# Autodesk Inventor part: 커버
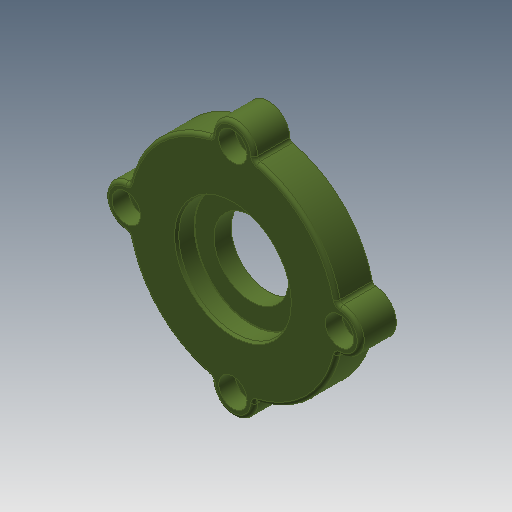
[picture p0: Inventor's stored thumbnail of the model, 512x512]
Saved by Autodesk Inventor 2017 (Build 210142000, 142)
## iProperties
Created: 2016-06
Part Number: 커버
Material: 알루미늄 6061
Document SubType Name: Modeling
Designer: mduedu
Density: 2.71 g/cm^3
Appearance: 올리브 녹색
Author: mduedu
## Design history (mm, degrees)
sketch "스케치1"
  geometry: C1 r 30 at (0, 0); 1 further point
  constraints: 1 centre point, 1 coincident
  dimensions: "d0" = 60 diameter of C1
extrude "돌출1" new body sketch "스케치1" distance "d2" = 10; taper "d3" = 0 deg
sketch "스케치5"
  geometry: C1 r 6 at (0, 30); 2 further points
  constraints: 2 vertical alignment, 1 centre point, 1 other
  dimensions: "d61" = 12 diameter of C1
extrude "돌출3" join sketch "스케치5" stored distance "d62" = 10; taper "d63" = 0 deg
sketch "스케치2"
  geometry: C1 r 21 at (0, 0); 1 further point
  constraints: 1 centre point, 1 coincident
  dimensions: "d4" = 42 diameter of C1
extrude "돌출2" join sketch "스케치2" distance "d6" = 3; taper "d7" = 0 deg
hole "구멍1" diameter "d11" = 35; stored, may be unused: countersink angle "d15" = 90 deg, drill point angle "d17" = 0 deg; dims "d9" = 10, "d10" = 10, "d12" = 6, "d13" = 4, "d14" = 2, "d16" = 3
hole "구멍2" diameter "d20" = 32; stored, may be unused: countersink angle "d24" = 90 deg, drill point angle "d26" = 0 deg; dims "d21" = 6, "d22" = 4, "d23" = 2, "d25" = 5.2, "d67" = 10, "d68" = 10
hole "구멍3" diameter "d29" = 21; stored, may be unused: countersink angle "d33" = 90 deg, drill point angle "d35" = 0 deg; dims "d27" = 10, "d28" = 10, "d30" = 6, "d31" = 4, "d32" = 2, "d34" = 5
fillet "모깎기2" dims "d36" = 3
fillet "모깎기3" dims "d37" = 0.1
chamfer "모따기1" distance "d38" = 0.75; stored, may be unused: second distance "d39" = 2, angle "d40" = 30 deg
chamfer "모따기2" distance "d42" = 0.5; stored, may be unused: second distance "d43" = 2, angle "d44" = 30 deg
sketch "스케치6"
  geometry: A1 r 30 centre (0, 0) between (29.4, 5.97) and (5.97, 29.4) reference; 3 further points
  constraints: 2 vertical alignment, 1 coincident, 3 other
hole "구멍5" sketch "스케치6" at (0, 30) diameter "d69" = 4.5; stored, may be unused: countersink angle "d73" = 90 deg, drill point angle "d75" = 118 deg; dims "d70" = 6, "d71" = 8, "d72" = 4.6, "d74" = 8
fillet "모깎기5" dims "d79" = 1
fillet "모깎기6" dims "d80" = 1
node "솔리드1"
pattern_circular "원형 패턴1" dims angle "d65" = 360 deg
pattern_circular "원형 패턴2" dims angle "d77" = 360 deg
node "투영된 루프1"
